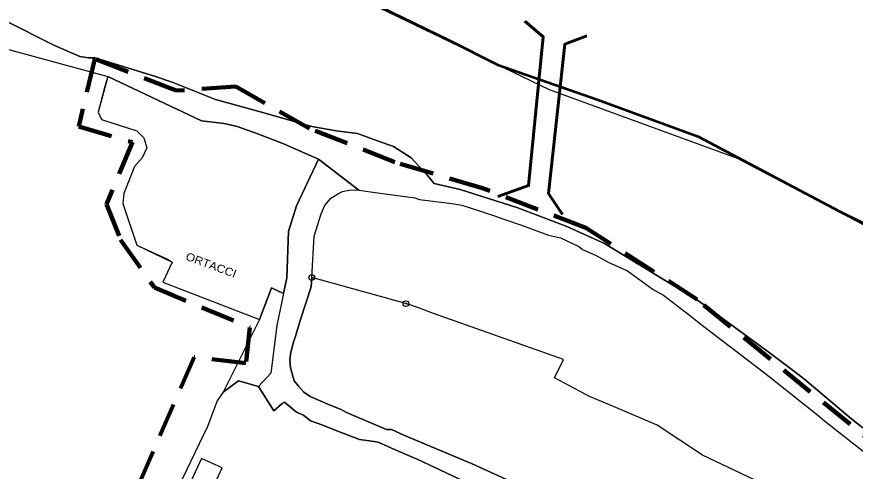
# Model space of a CAD drawing. Extents: x 654952 to 658955, y 890426 to 894481.
# Drawn here: x 657687.5 to 657981, y 894028.8 to 894187.9 of the extents above; entities that cross this region are included whole.
import ezdxf

# ---------------------------------------------------------------- set-up
doc = ezdxf.new("R2010")
doc.units = 0
doc.header["$LTSCALE"] = 4
doc.header["$PDMODE"] = 32
doc.header["$PDSIZE"] = 2
doc.linetypes.add('MEDIUM_DASHED', pattern=[4.5, 3, -1.5])
doc.linetypes.add('SHORT_DASHED', pattern=[2.7, 1.5, -1.2])
for name, color, linetype, lineweight in [('11', 7, 'Continuous', 25), ('35', 7, 'Continuous', 25), ('41', 7, 'SHORT_DASHED', 80), ('43', 7, 'Continuous', 25), ('5', 7, 'Continuous', 25), ('59', 7, 'Continuous', 53), ('6', 7, 'Continuous', 25), ('7', 7, 'MEDIUM_DASHED', 100), ('9', 7, 'Continuous', 25)]:
    doc.layers.add(name, color=color, linetype=linetype, lineweight=lineweight)
doc.layers.add('58', color=7, linetype='Continuous')

msp = doc.modelspace()

# ---------------------------------------------------------------- linework, layer by layer
at = {"layer": '11'}
for p, q in [((657793.15, 894138.03), (657807.26, 894127.2)), ((657772.51, 894081.94), (657759.76, 894056.44))]:
    msp.add_line(p, q, dxfattribs=at)
for points in [[(657823.74, 894087.44), (657790.77, 894096.6), (657790.58, 894093.33), (657786.86, 894081.94), (657785.24, 894076.44)], [(657952.62, 893967.44), (657979.85, 893948.55), (657994.86, 893959.44), (658007.24, 893972.94), (658005.62, 893974.44), (658004.36, 893972.94), (658003.12, 893974.44), (658002.71, 893973.96), (657994.24, 893980.94), (657997.74, 893984.44), (657963.86, 894011.94), (657950.62, 894023.44), (657927.49, 894034.44), (657911.62, 894044.94), (657896.36, 894051.44), (657887.99, 894054.94), (657875.74, 894061.44), (657878.86, 894067.92), (657833.36, 894083.94), (657828.12, 894085.94), (657823.74, 894087.44)], [(657785.24, 894076.44), (657784.36, 894073.94), (657783.49, 894070.44), (657783.12, 894067.94), (657783.37, 894064.94), (657784.62, 894060.44), (657786.24, 894058.44), (657787.99, 894056.44), (657790.24, 894054.94), (657797.24, 894051.94), (657801.12, 894050.44), (657802.74, 894049.44), (657806.24, 894047.94), (657816.99, 894043.44), (657818.74, 894043.44), (657822.99, 894041.44), (657845.49, 894031.94), (657846.74, 894031.44), (657858.99, 894025.94)]]:
    msp.add_lwpolyline(points, dxfattribs=at)
msp.add_point((657823.74, 894087.44), dxfattribs=at)
at = {"layer": '35'}
msp.add_lwpolyline([(657677.23, 894178.36), (657719.38, 894166.94), (657716.01, 894154.44), (657717.14, 894151.94), (657729.51, 894147.94), (657732.01, 894145.44), (657733.01, 894141.94), (657731.39, 894138.44), (657728.76, 894135.44), (657725.01, 894125.94), (657724.64, 894122.44), (657729.52, 894107.91), (657741.88, 894101.94), (657738.64, 894094.94), (657772.51, 894081.94), (657776.64, 894092.94), (657780.88, 894090.94), (657778.59, 894079.76), (657776.49, 894063.09), (657772.14, 894058.44), (657765.14, 894060.44), (657759.76, 894056.44), (657757.64, 894053.44), (657754.26, 894044.44), (657742.51, 894019.94)], dxfattribs=at)
at = {"layer": '41', "linetype": 'Continuous', "lineweight": 60}
for points in [[(657865.41, 894186.34), (657871.83, 894180.82), (657866.66, 894128.79), (657855.93, 894124.95)], [(657887.11, 894181.17), (657879.3, 894178.23), (657873.67, 894125.97), (657878.5, 894118.6)]]:
    msp.add_lwpolyline(points, dxfattribs=at)
at = {"layer": '43'}
for points in [[(658266.41, 893937.09), (658214.83, 893967.25), (658194.33, 893989.87), (658168.89, 894009.06), (658121.55, 894033.74), (658121.55, 894033.74), (658085.51, 894058.42), (658016.08, 894099.23), (658016.08, 894099.23), (657987.82, 894112.94), (657939.76, 894138.3), (657874.04, 894162.29), (657811.4, 894192.37), (657779.35, 894208.91), (657757.45, 894224.67), (657703.03, 894250.03), (657703.03, 894250.03), (657646.5, 894254.15)], [(657619.76, 894218.44), (657621.51, 894217.44), (657633.01, 894211.44), (657649.26, 894202.94), (657669.51, 894193.44), (657683.63, 894186.44), (657700.51, 894177.94), (657709.63, 894173.94), (657712.63, 894173.44), (657715.01, 894173.44)], [(657715.01, 894173.44), (657736.13, 894166.94), (657741.88, 894164.94), (657757.13, 894158.94), (657773.13, 894154.44), (657790.76, 894149.44), (657799.38, 894147.94), (657806.76, 894146.94), (657813.76, 894144.44), (657819.38, 894142.44), (657825.63, 894138.44), (657831.13, 894132.44), (657833.63, 894129.44), (657842.76, 894127.44), (657862.88, 894120.94), (657880.01, 894114.44), (657893.26, 894108.44), (657926.13, 894088.44), (657938.76, 894079.19), (657951.38, 894069.94), (657957.38, 894065.44), (657963.38, 894060.94), (657979.26, 894047.44), (657983.63, 894043.94)]]:
    msp.add_lwpolyline(points, dxfattribs=at)
at = {"layer": '5'}
for points in [[(657715.01, 894173.44), (657712.63, 894173.44), (657709.63, 894173.94), (657700.51, 894177.94), (657683.63, 894186.44), (657677.23, 894178.36), (657719.38, 894166.94), (657752.14, 894151.44)], [(657833.63, 894129.44), (657831.13, 894132.44), (657825.63, 894138.44), (657819.38, 894142.44), (657813.76, 894144.44), (657806.76, 894146.94), (657799.38, 894147.94), (657790.76, 894149.44), (657773.13, 894154.44), (657757.13, 894158.94), (657741.88, 894164.94), (657736.13, 894166.94), (657715.01, 894173.44)], [(657752.14, 894151.44), (657760.14, 894150.44), (657764.64, 894149.44), (657771.51, 894146.94), (657780.64, 894143.44), (657793.15, 894138.03), (657807.26, 894127.2)], [(657791.59, 894111.1), (657794.06, 894118.92), (657795.39, 894121.82), (657797.51, 894124.31), (657800.12, 894125.94), (657801.55, 894126.75), (657803.72, 894127.22), (657805.82, 894127.33), (657807.26, 894127.2), (657793.15, 894138.03), (657785.48, 894121.63)], [(657807.26, 894127.2), (657808.99, 894126.94), (657812.12, 894126.44), (657826.86, 894124.44), (657828.49, 894123.94)], [(657983.63, 894043.94), (657979.26, 894047.44), (657963.38, 894060.94), (657957.38, 894065.44), (657951.38, 894069.94), (657938.76, 894079.19), (657926.13, 894088.44), (657893.26, 894108.44), (657880.01, 894114.44), (657862.88, 894120.94), (657842.76, 894127.44), (657833.63, 894129.44)], [(657828.49, 894123.94), (657839.86, 894122.44), (657843.36, 894121.94), (657849.49, 894119.94), (657853.99, 894118.44), (657858.36, 894116.94), (657864.24, 894114.94), (657873.62, 894111.44), (657877.86, 894110.44), (657884.24, 894107.44), (657885.49, 894106.44), (657890.12, 894104.44), (657894.49, 894101.94), (657901.24, 894098.94), (657910.24, 894092.44), (657913.86, 894090.44), (657922.99, 894083.44), (657927.99, 894079.44), (657945.74, 894065.94), (657950.86, 894061.94), (657967.86, 894048.44), (657970.24, 894046.44)], [(657785.48, 894121.63), (657782.68, 894112.74), (657782.01, 894096.44), (657780.88, 894090.94), (657776.64, 894092.94), (657775.14, 894088.94), (657772.51, 894081.94), (657759.76, 894056.44), (657765.14, 894060.44), (657772.14, 894058.44), (657777.51, 894049.94)], [(657797.24, 894051.94), (657790.24, 894054.94), (657787.99, 894056.44), (657786.24, 894058.44), (657784.62, 894060.44), (657783.37, 894064.94), (657783.12, 894067.94), (657783.49, 894070.44), (657784.36, 894073.94), (657785.24, 894076.44), (657786.86, 894081.94), (657790.58, 894093.33), (657790.77, 894096.6), (657791.59, 894111.1)], [(657777.51, 894049.94), (657780.38, 894052.44), (657781.26, 894052.94), (657785.39, 894049.44)], [(657858.99, 894025.94), (657846.74, 894031.44), (657845.49, 894031.94), (657822.99, 894041.44), (657818.74, 894043.44), (657816.99, 894043.44), (657806.24, 894047.94), (657802.74, 894049.44), (657801.12, 894050.44), (657797.24, 894051.94)], [(657785.39, 894049.44), (657787.88, 894048.44), (657790.38, 894046.44), (657794.64, 894044.94), (657799.51, 894042.94), (657807.51, 894039.94), (657811.01, 894039.44), (657814.01, 894038.94), (657819.76, 894036.44), (657827.88, 894032.94), (657851.67, 894021.72), (657861.64, 894016.94), (657863.51, 894015.44), (657865.26, 894013.94), (657877.25, 894006.93)], [(657970.24, 894046.44), (657989.24, 894031.44)]]:
    msp.add_lwpolyline(points, dxfattribs=at)
at = {"layer": '59'}
msp.add_lwpolyline([(657431.84, 894352.05), (657500.4, 894338.39), (657554.69, 894302.38), (657602.47, 894274.44), (657631.94, 894262.63), (657689.95, 894257.67), (657735.24, 894235.94), (657762.24, 894219.79), (657775.57, 894210.48), (657838.55, 894179.75), (657855.92, 894171.05), (657890.67, 894158.95), (657926.03, 894145.91), (657975.36, 894119.83), (658011.03, 894102.14), (658033.37, 894087.55)], dxfattribs=at)
at = {"layer": '6'}
msp.add_lwpolyline([(657752.2, 894033.29), (657745.71, 894019.11), (657750.26, 894017.03), (657754.17, 894025.57), (657756.89, 894024.33), (657759.47, 894029.96)], close=True, dxfattribs=at)
at = {"layer": '7'}
msp.add_lwpolyline([(658035, 893999.74), (657925.71, 894088.89), (657886.73, 894113.96), (657850.53, 894127.89), (657819.9, 894136.94), (657789.97, 894148.78), (657764.22, 894163.41), (657743.34, 894162.02), (657714.8, 894173.16), (657709.23, 894149.48), (657728.02, 894143.91), (657718.97, 894122.32), (657723.85, 894109.78), (657735.68, 894093.06), (657769.09, 894079.13), (657767.7, 894066.6), (657749.6, 894068.69), (657702.96, 893961.43)], dxfattribs=at)
msp.add_lwpolyline([(658035, 893999.74), (657925.71, 894088.89), (657886.73, 894113.96), (657850.53, 894127.89), (657819.9, 894136.94), (657789.97, 894148.78), (657764.22, 894163.41), (657743.34, 894162.02), (657714.8, 894173.16), (657709.23, 894149.48), (657728.02, 894143.91), (657718.97, 894122.32), (657723.85, 894109.78), (657735.68, 894093.06), (657769.09, 894079.13), (657767.7, 894066.6), (657749.6, 894068.69), (657702.96, 893961.43)], dxfattribs=at)
at = {"layer": '9'}
for p, q in [((657790.77, 894096.6), (657791.59, 894111.1)), ((657823.74, 894087.44), (657790.77, 894096.6))]:
    msp.add_line(p, q, dxfattribs=at)
for points in [[(657719.38, 894166.94), (657718.38, 894163.44), (657716.01, 894154.44), (657717.14, 894151.94), (657729.51, 894147.94), (657732.01, 894145.44), (657733.01, 894141.94), (657731.39, 894138.44), (657728.76, 894135.44), (657725.01, 894125.94), (657724.64, 894122.44), (657729.52, 894107.91), (657740.51, 894102.94), (657741.88, 894101.94), (657738.64, 894094.94), (657772.51, 894081.94), (657775.14, 894088.94), (657776.64, 894092.94), (657780.88, 894090.94), (657782.01, 894096.44)], [(657793.15, 894138.03), (657780.64, 894143.44), (657771.51, 894146.94), (657764.64, 894149.44), (657760.14, 894150.44), (657752.14, 894151.44), (657719.38, 894166.94)], [(657782.01, 894096.44), (657782.68, 894112.74), (657785.48, 894121.63), (657793.15, 894138.03)], [(657791.59, 894111.1), (657794.06, 894118.92), (657795.39, 894121.82), (657797.51, 894124.31), (657800.12, 894125.94), (657801.55, 894126.75), (657803.72, 894127.22), (657805.82, 894127.33), (657807.26, 894127.2), (657808.99, 894126.94), (657812.12, 894126.44), (657826.86, 894124.44), (657828.49, 894123.94)], [(657828.49, 894123.94), (657839.86, 894122.44), (657843.36, 894121.94), (657849.49, 894119.94), (657853.99, 894118.44), (657858.36, 894116.94), (657864.24, 894114.94), (657873.62, 894111.44), (657877.86, 894110.44), (657884.24, 894107.44), (657885.49, 894106.44), (657890.12, 894104.44), (657894.49, 894101.94), (657901.24, 894098.94), (657910.24, 894092.44), (657913.86, 894090.44), (657922.99, 894083.44), (657927.99, 894079.44), (657945.74, 894065.94), (657950.86, 894061.94), (657967.86, 894048.44), (657970.24, 894046.44)], [(657997.74, 893984.44), (657963.86, 894011.94), (657950.62, 894023.44), (657927.49, 894034.44), (657911.62, 894044.94), (657896.36, 894051.44), (657887.99, 894054.94), (657875.74, 894061.44), (657878.86, 894067.92), (657833.36, 894083.94), (657828.12, 894085.94), (657823.74, 894087.44)], [(657799.51, 894042.94), (657794.64, 894044.94), (657790.38, 894046.44), (657787.88, 894048.44), (657785.39, 894049.44), (657781.26, 894052.94), (657780.38, 894052.44), (657777.51, 894049.94), (657772.14, 894058.44), (657765.14, 894060.44), (657759.76, 894056.44), (657757.64, 894053.44), (657754.26, 894044.44)], [(657970.24, 894046.44), (657989.24, 894031.44)], [(657754.26, 894044.44), (657742.51, 894019.94), (657778.14, 894001.94), (657785.26, 893998.94), (657792.51, 893995.44), (657793.88, 893994.44), (657800.51, 893990.44), (657803.01, 893987.94), (657816.76, 893981.94), (657820.51, 893979.44), (657831.64, 893972.94), (657834.38, 893972.44), (657837.26, 893971.44), (657842.64, 893971.44), (657846.38, 893972.44)], [(657846.38, 893972.44), (657847.26, 893972.94), (657849.13, 893973.44), (657851.51, 893975.44), (657852.88, 893976.94), (657856.26, 893979.94), (657857.01, 893981.44), (657857.91, 893982.84), (657853.76, 893987.42), (657835.75, 894007.29), (657851.67, 894021.72), (657827.88, 894032.94), (657819.76, 894036.44), (657814.01, 894038.94), (657811.01, 894039.44), (657807.51, 894039.94), (657799.51, 894042.94)]]:
    msp.add_lwpolyline(points, dxfattribs=at)
msp.add_point((657790.77, 894096.6), dxfattribs=at)

# ---------------------------------------------------------------- texts
at = {"layer": '58', "width": 1.1}
msp.add_text('ORTACCI', height=2.801, rotation=339.594, dxfattribs=at).set_placement((657746.39, 894102.89))

doc.saveas('drawing.dxf')
